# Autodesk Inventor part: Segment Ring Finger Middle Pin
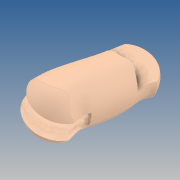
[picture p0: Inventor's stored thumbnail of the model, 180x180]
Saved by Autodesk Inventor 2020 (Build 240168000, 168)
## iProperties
Created: 2019-10
Part Number: Segment Ring Finger Middle Pin
Material: GFRP
Document SubType Name: Modeling
Designer: yello
Density: 1.75 g/cm^3
Appearance: Default
Author: yello
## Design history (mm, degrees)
feature "Paliczek SE"
body "Solid1"
